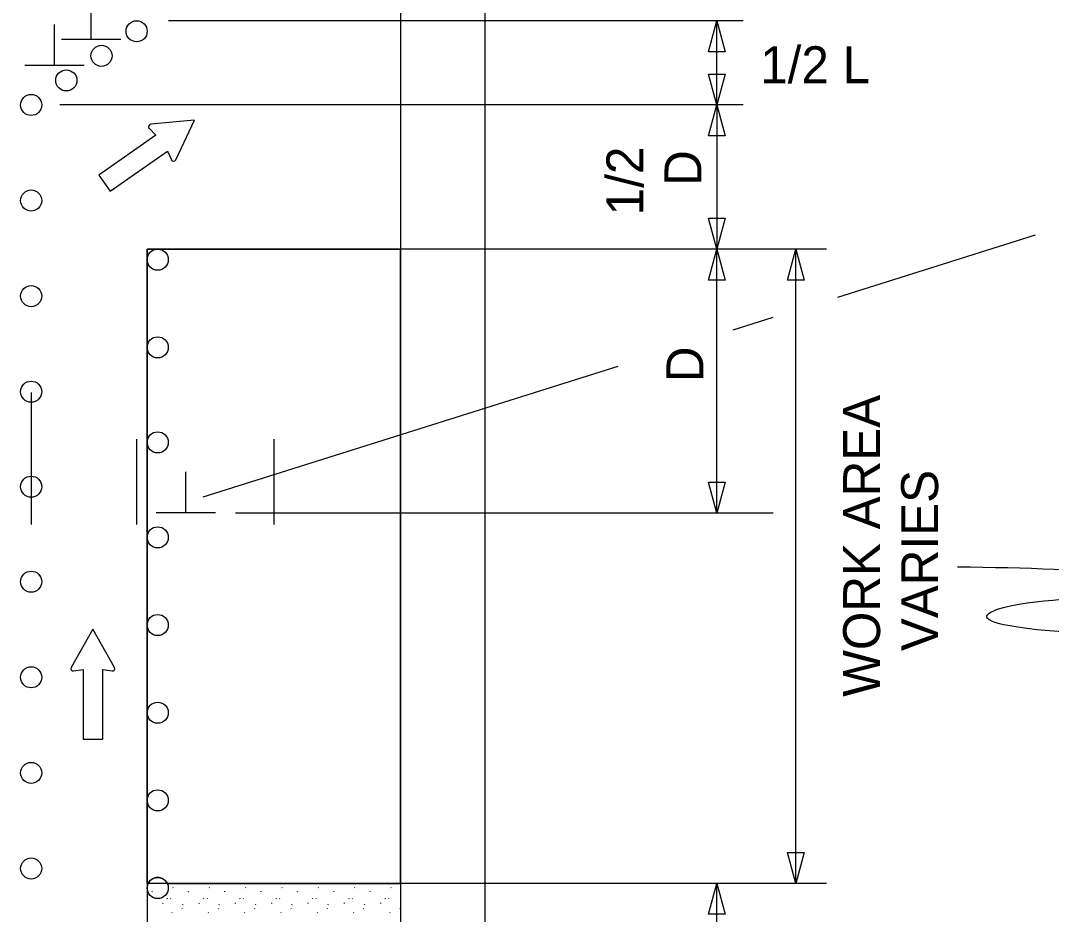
# Model space of a CAD drawing. Extents: x 16748 to 18475, y 7008 to 8262.
# Drawn here: x 17041.1 to 17236.5, y 7769.6 to 7939 of the extents above; entities that cross this region are included whole.
import ezdxf

# ---------------------------------------------------------------- set-up
doc = ezdxf.new("R2010")
doc.units = 0
for name, color, linetype in [('ALI_LEGAL_EX', 7, 'Continuous'), ('MT_SCRATCH_LEVEL_A', 7, 'Continuous'), ('MT_SCRATCH_LEVEL_E', 7, 'Continuous'), ('PAVT_EDGE_EX', 7, 'Continuous'), ('TRAFFIC_SIGNS_PR', 7, 'Continuous'), ('TYPICAL_TEXT_DIMEN_PR', 7, 'Continuous')]:
    doc.layers.add(name, color=color, linetype=linetype)

msp = doc.modelspace()

# ---------------------------------------------------------------- linework, layer by layer
at = {"layer": 'ALI_LEGAL_EX'}
for points in [[(17043.08, 7868.47), (17043.08, 7843.47)], [(17063.08, 7859.65), (17063.08, 7843.47)], [(17089.08, 7859.65), (17089.08, 7843.47)]]:
    msp.add_lwpolyline(points, dxfattribs=at)
at = {"layer": 'MT_SCRATCH_LEVEL_A'}
for p, q in [((17069.94, 7774.72), (17069.99, 7774.64)), ((17076.83, 7774.72), (17076.88, 7774.64)), ((17083.71, 7774.72), (17083.76, 7774.64)), ((17090.6, 7774.72), (17090.65, 7774.64)), ((17097.49, 7774.72), (17097.54, 7774.64)), ((17104.38, 7774.72), (17104.43, 7774.64)), ((17111.26, 7774.72), (17111.31, 7774.64)), ((17066.01, 7773.88), (17066.06, 7774)), ((17068.79, 7772.65), (17068.84, 7772.57)), ((17069.53, 7772.62), (17069.58, 7772.54)), ((17072.9, 7773.88), (17072.95, 7774)), ((17075.68, 7772.65), (17075.73, 7772.57)), ((17076.42, 7772.62), (17076.47, 7772.54)), ((17079.78, 7773.88), (17079.83, 7774)), ((17082.57, 7772.65), (17082.62, 7772.57)), ((17083.3, 7772.62), (17083.36, 7772.54)), ((17086.67, 7773.88), (17086.72, 7774)), ((17089.46, 7772.65), (17089.51, 7772.57)), ((17090.19, 7772.62), (17090.24, 7772.54)), ((17093.56, 7773.88), (17093.61, 7774)), ((17096.34, 7772.65), (17096.39, 7772.57)), ((17097.08, 7772.62), (17097.13, 7772.54)), ((17100.45, 7773.88), (17100.5, 7774)), ((17103.23, 7772.65), (17103.28, 7772.57)), ((17103.97, 7772.62), (17104.02, 7772.54)), ((17107.33, 7773.88), (17107.39, 7774)), ((17110.12, 7772.65), (17110.17, 7772.57)), ((17110.85, 7772.62), (17110.91, 7772.54)), ((17068.03, 7771.69), (17068.08, 7771.8)), ((17071.67, 7770.74), (17071.73, 7770.66)), ((17071.85, 7771.39), (17071.9, 7771.51)), ((17074.92, 7771.69), (17074.97, 7771.8)), ((17078.56, 7770.74), (17078.61, 7770.66)), ((17078.74, 7771.39), (17078.79, 7771.51)), ((17081.8, 7771.69), (17081.85, 7771.8)), ((17085.45, 7770.74), (17085.5, 7770.66)), ((17085.62, 7771.39), (17085.67, 7771.51)), ((17088.69, 7771.69), (17088.74, 7771.8)), ((17092.34, 7770.74), (17092.39, 7770.66)), ((17092.51, 7771.39), (17092.56, 7771.51)), ((17095.58, 7771.69), (17095.63, 7771.8)), ((17099.22, 7770.74), (17099.28, 7770.66)), ((17099.4, 7771.39), (17099.45, 7771.51)), ((17102.47, 7771.69), (17102.52, 7771.8)), ((17106.11, 7770.74), (17106.16, 7770.66)), ((17106.28, 7771.39), (17106.34, 7771.51)), ((17109.35, 7771.69), (17109.4, 7771.8)), ((17113, 7770.74), (17113.05, 7770.66)), ((17069.75, 7769.87), (17069.8, 7769.98)), ((17076.64, 7769.87), (17076.69, 7769.98)), ((17083.53, 7769.87), (17083.58, 7769.98)), ((17090.41, 7769.87), (17090.46, 7769.98)), ((17097.3, 7769.87), (17097.35, 7769.98)), ((17104.19, 7769.87), (17104.24, 7769.98)), ((17111.08, 7769.87), (17111.13, 7769.98))]:
    msp.add_line(p, q, dxfattribs=at)
msp.add_lwpolyline([(17113.08, 7775.48), (17065.08, 7775.48), (17065.08, 7895.65), (17113.08, 7895.65)], close=True, dxfattribs=at)
at = {"layer": 'MT_SCRATCH_LEVEL_E'}
for p, q in [((17074.05, 7920.11), (17065.76, 7919.34)), ((17074.05, 7920.11), (17065.76, 7919.34)), ((17070.49, 7912.57), (17074.05, 7920.11)), ((17070.49, 7912.57), (17074.05, 7920.11)), ((17066.75, 7917.27), (17055.89, 7909.68)), ((17066.75, 7917.27), (17055.89, 7909.68)), ((17065.48, 7918.55), (17066.75, 7917.27)), ((17065.48, 7918.55), (17066.75, 7917.27)), ((17058.03, 7906.61), (17068.9, 7914.21)), ((17058.03, 7906.61), (17068.9, 7914.21)), ((17068.9, 7914.21), (17069.66, 7912.57)), ((17068.9, 7914.21), (17069.66, 7912.57)), ((17055.89, 7909.68), (17058.03, 7906.61)), ((17055.89, 7909.68), (17058.03, 7906.61)), ((17054.76, 7823.64), (17050.65, 7816.4)), ((17054.76, 7823.64), (17050.65, 7816.4)), ((17058.91, 7816.4), (17054.76, 7823.64)), ((17058.91, 7816.4), (17054.76, 7823.64)), ((17051.14, 7815.72), (17052.91, 7816.03)), ((17051.14, 7815.72), (17052.91, 7816.03)), ((17052.91, 7816.03), (17052.91, 7802.78)), ((17052.91, 7816.03), (17052.91, 7802.78)), ((17056.65, 7802.78), (17056.65, 7816.03)), ((17056.65, 7816.03), (17058.43, 7815.72)), ((17056.65, 7802.78), (17056.65, 7816.03)), ((17056.65, 7816.03), (17058.43, 7815.72)), ((17052.91, 7802.78), (17056.65, 7802.78)), ((17052.91, 7802.78), (17056.65, 7802.78))]:
    msp.add_line(p, q, dxfattribs=at)
for centre, start, end in [((17065.81, 7918.87), 95.3561, 224.895), ((17065.81, 7918.87), 95.3561, 224.895), ((17070.07, 7912.77), 204.9674, 334.7043), ((17070.07, 7912.77), 204.9674, 334.7043), ((17051.06, 7816.18), 150.4248, 279.9638), ((17051.06, 7816.18), 150.4248, 279.9638), ((17058.5, 7816.18), 260.0362, 29.7731), ((17058.5, 7816.18), 260.0362, 29.7731)]:
    msp.add_arc(centre, 0.463, start, end, dxfattribs=at)
at = {"layer": 'PAVT_EDGE_EX'}
for p, q in [((17113.08, 8185.96), (17113.08, 7352.54)), ((17129.08, 8185.96), (17129.08, 7352.54)), ((17113.08, 7895.65), (17065.08, 7895.65)), ((17113.08, 7775.48), (17113.08, 7895.65)), ((17065.08, 7859.65), (17065.08, 7743.42))]:
    msp.add_line(p, q, dxfattribs=at)
for points in [[(17065.08, 7895.65), (17065.08, 7775.48), (17065.29, 7775.48)], [(17068.87, 7775.48), (17113.08, 7775.48)]]:
    msp.add_lwpolyline(points, dxfattribs=at)
msp.add_arc((17067.08, 7774.59), 2, 26.3274, 153.6726, dxfattribs=at)
at = {"layer": 'TRAFFIC_SIGNS_PR'}
for centre in [(17063.08, 7936.94), (17056.41, 7932.28), (17049.75, 7927.62), (17043.08, 7922.97), (17043.08, 7904.86), (17067.08, 7893.65), (17043.08, 7886.75), (17067.08, 7877.04), (17043.08, 7868.64), (17067.08, 7859.04), (17043.08, 7850.64), (17067.08, 7841.04), (17043.08, 7832.64), (17067.08, 7824.43), (17043.08, 7814.52), (17067.08, 7807.81), (17043.08, 7796.41), (17067.08, 7791.2), (17043.08, 7778.3), (17067.08, 7774.59)]:
    msp.add_circle(centre, 2, dxfattribs=at)
at = {"layer": 'TYPICAL_TEXT_DIMEN_PR'}
for p, q in [((17054.46, 7935.37), (17054.46, 7943.16)), ((17178.08, 7938.94), (17069.15, 7938.94)), ((17171.51, 7933.07), (17173.08, 7938.94)), ((17173.08, 7922.97), (17173.08, 7938.94)), ((17173.08, 7938.94), (17174.65, 7933.07)), ((17047.53, 7930.42), (17047.53, 7938.2)), ((17060.08, 7935.37), (17048.83, 7935.37)), ((17173.08, 7933.07), (17171.51, 7933.07)), ((17174.65, 7933.07), (17173.08, 7933.07)), ((17053.15, 7930.42), (17041.9, 7930.42)), ((17173.08, 7922.97), (17171.51, 7928.83)), ((17171.51, 7928.83), (17173.08, 7928.83)), ((17173.08, 7928.83), (17174.65, 7928.83)), ((17174.65, 7928.83), (17173.08, 7922.97)), ((17178.08, 7922.97), (17048.53, 7922.97)), ((17171.51, 7917.11), (17173.08, 7922.97)), ((17173.08, 7922.97), (17174.65, 7917.11)), ((17173.08, 7922.97), (17173.08, 7895.65)), ((17173.08, 7917.11), (17171.51, 7917.11)), ((17174.65, 7917.11), (17173.08, 7917.11)), ((17173.08, 7895.65), (17171.51, 7901.51)), ((17171.51, 7901.51), (17173.08, 7901.51)), ((17173.08, 7901.51), (17174.65, 7901.51)), ((17174.65, 7901.51), (17173.08, 7895.65)), ((17233.45, 7898.33), (17195.96, 7886.52)), ((17193.88, 7895.65), (17065.08, 7895.65)), ((17171.51, 7889.79), (17173.08, 7895.65)), ((17173.08, 7845.65), (17173.08, 7895.65)), ((17173.08, 7895.65), (17174.65, 7889.79)), ((17186.51, 7889.79), (17188.08, 7895.65)), ((17188.08, 7775.48), (17188.08, 7895.65)), ((17188.08, 7895.65), (17189.65, 7889.79)), ((17173.08, 7889.79), (17171.51, 7889.79)), ((17174.65, 7889.79), (17173.08, 7889.79)), ((17188.08, 7889.79), (17186.51, 7889.79)), ((17189.65, 7889.79), (17188.08, 7889.79)), ((17183.72, 7882.67), (17176.09, 7880.27)), ((17154.28, 7873.4), (17075.62, 7848.64)), ((17072.41, 7845.68), (17072.41, 7853.47)), ((17173.08, 7845.65), (17171.51, 7851.51)), ((17171.51, 7851.51), (17173.08, 7851.51)), ((17173.08, 7851.51), (17174.65, 7851.51)), ((17174.65, 7851.51), (17173.08, 7845.65)), ((17078.03, 7845.68), (17066.78, 7845.68)), ((17183.74, 7845.65), (17081.84, 7845.65)), ((17188.08, 7775.48), (17186.51, 7781.34)), ((17186.51, 7781.34), (17188.08, 7781.34)), ((17188.08, 7781.34), (17189.65, 7781.34)), ((17189.65, 7781.34), (17188.08, 7775.48)), ((17193.88, 7775.48), (17113.08, 7775.48)), ((17171.51, 7769.61), (17173.08, 7775.48)), ((17173.08, 7743.42), (17173.08, 7775.48)), ((17173.08, 7775.48), (17174.65, 7769.61)), ((17173.08, 7769.61), (17171.51, 7769.61)), ((17174.65, 7769.61), (17173.08, 7769.61))]:
    msp.add_line(p, q, dxfattribs=at)
msp.add_open_spline([(17305.29, 7821.56), (17220.51, 7821.56), (17220.51, 7829.44), (17256.47, 7829.44), (17256.47, 7834.43), (17231.65, 7835.26), (17218.73, 7835.41)], degree=3, dxfattribs=at)

# ---------------------------------------------------------------- texts
msp.add_text('1/2 L', height=7, dxfattribs=at).set_placement((17181.3, 7927.09))
for s, p in [('1/2', (17159.15, 7902.07)), ('D', (17170.15, 7907.64)), ('D', (17170.52, 7870.44)), ('WORK AREA', (17204.03, 7810.84)), ('VARIES', (17215.03, 7819.48))]:
    msp.add_text(s, height=7, rotation=90, dxfattribs=at).set_placement(p)

doc.saveas('drawing.dxf')
